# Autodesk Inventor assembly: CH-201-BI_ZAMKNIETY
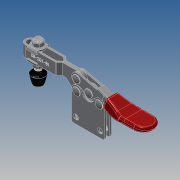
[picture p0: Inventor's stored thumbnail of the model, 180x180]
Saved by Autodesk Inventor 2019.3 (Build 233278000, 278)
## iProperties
Company: ·L?¤¤?
Created: 2010-06
Part Number: CH-201-BI_ZAMKNIETY
Material: Ogólny
Description: STEP AP203
Document SubType Name: Assembly
Designer: CADENGINEERING4
Sending System: SolidWorks 2005179
Preprocessor: SwSTEP 2.0
Title: CH-201-BI.STEP
Author: ·L?¥Î?
Revision Number: ANY
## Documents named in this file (9)
- E:\STRONA\Horizontal toggle clamp\CH-201-BI\CH-201-BI_ZAMKNIETY.iam
- E:\STRONA\Horizontal toggle clamp\CH-201-BI\14134-02___.ipt
- E:\STRONA\Horizontal toggle clamp\CH-201-BI\201-B-04___.ipt
- E:\STRONA\Horizontal toggle clamp\CH-201-BI\201-B-06___.ipt
- E:\STRONA\Horizontal toggle clamp\CH-201-BI\201-BI-02___.ipt
- E:\STRONA\Horizontal toggle clamp\CH-201-BI\FW140___.ipt
- E:\STRONA\Horizontal toggle clamp\CH-201-BI\14134___.ipt
- E:\STRONA\Horizontal toggle clamp\CH-201-BI\201-B___.iam
- E:\STRONA\Horizontal toggle clamp\CH-201-BI\201-BI-01___.ipt
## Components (14 placed, 14 different names)
1. 14134-02_??_1 — Równoległe:3, Zestawiające:1, Zestawiające:5
2. 201-B-04_??_2 — Zestawiające:11, Zestawiające:12, Zestawiające:13
3. 201-B-06_??_3 — Zestawiające:20, Zestawiające:21
4. 201-BI-02_??_4 — Równoległe:1, Zestawiające:7, Zestawiające:8, Zestawiające:9, Zestawiające:10, Zestawiające:22, Zestawiające:25, Zestawiające:26
5. FW140_??_5 — Równoległe:2, Zestawiające:2, Zestawiające:6, Zestawiające:7
6. 14134_??_6 — Równoległe:3, Zestawiające:1, Zestawiające:2, Zestawiające:3, Zestawiające:4, Zestawiające:9
7. 201-B-06_??_7 — Zestawiające:16, Zestawiające:17
8. 201-B-04_??_8 — Zestawiające:11, Zestawiające:12, Zestawiające:13, Zestawiające:14, Zestawiające:15, Zestawiające:18, Zestawiające:19
9. 201-B_??_9 [sub-assembly] — Zestawiające:18, Zestawiające:19, Zestawiające:20, Zestawiające:21, Zestawiające:26, Zestawiające:27, Przejściowe:1
10. 14134-02_??_10 — Zestawiające:3, Zestawiające:6
11. FW140_??_11 — Równoległe:1, Równoległe:2, Zestawiające:4, Zestawiające:5, Zestawiające:8
12. 201-B-06_??_12 — Zestawiające:10, Zestawiające:27
13. 201-B-06_??_13 — Zestawiające:22, Zestawiające:23, Zestawiające:24
14. 201-BI-01_??_14 — Zestawiające:14, Zestawiające:15, Zestawiające:16, Zestawiające:17, Zestawiające:23, Zestawiające:24, Zestawiające:25, Przejściowe:1
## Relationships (31: Mate 27, Flush 3, Transitional 1)
- Równoległe:1 [Flush]: 201-BI-02_??_4 ↔ FW140_??_11
- Równoległe:2 [Flush]: FW140_??_5 ↔ FW140_??_11
- Równoległe:3 [Flush]: 14134-02_??_1 ↔ 14134_??_6
- Zestawiające:1 [Mate]: 14134-02_??_1 ↔ 14134_??_6
- Zestawiające:2 [Mate]: FW140_??_5 ↔ 14134_??_6
- Zestawiające:3 [Mate]: 14134_??_6 ↔ 14134-02_??_10
- Zestawiające:4 [Mate]: 14134_??_6 ↔ FW140_??_11
- Zestawiające:5 [Mate]: 14134-02_??_1 ↔ FW140_??_11
- Zestawiające:6 [Mate]: FW140_??_5 ↔ 14134-02_??_10
- Zestawiające:7 [Mate]: 201-BI-02_??_4 ↔ FW140_??_5
- Zestawiające:8 [Mate]: 201-BI-02_??_4 ↔ FW140_??_11
- Zestawiające:9 [Mate]: 201-BI-02_??_4 ↔ 14134_??_6
- Zestawiające:10 [Mate]: 201-BI-02_??_4 ↔ 201-B-06_??_12
- Zestawiające:11 [Mate]: 201-B-04_??_2 ↔ 201-B-04_??_8
- Zestawiające:12 [Mate]: 201-B-04_??_2 ↔ 201-B-04_??_8
- Zestawiające:13 [Mate]: 201-B-04_??_2 ↔ 201-B-04_??_8
- Zestawiające:14 [Mate]: 201-B-04_??_8 ↔ 201-BI-01_??_14
- Zestawiające:15 [Mate]: 201-B-04_??_8 ↔ 201-BI-01_??_14
- Zestawiające:16 [Mate]: 201-B-06_??_7 ↔ 201-BI-01_??_14
- Zestawiające:17 [Mate]: 201-B-06_??_7 ↔ 201-BI-01_??_14
- Zestawiające:18 [Mate]: 201-B-04_??_8 ↔ 201-B_??_9
- Zestawiające:19 [Mate]: 201-B-04_??_8 ↔ 201-B_??_9
- Zestawiające:20 [Mate]: 201-B-06_??_3 ↔ 201-B_??_9
- Zestawiające:21 [Mate]: 201-B-06_??_3 ↔ 201-B_??_9
- Zestawiające:22 [Mate]: 201-BI-02_??_4 ↔ 201-B-06_??_13
- Zestawiające:23 [Mate]: 201-B-06_??_13 ↔ 201-BI-01_??_14
- Zestawiające:24 [Mate]: 201-B-06_??_13 ↔ 201-BI-01_??_14
- Zestawiające:25 [Mate]: 201-BI-02_??_4 ↔ 201-BI-01_??_14
- Zestawiające:26 [Mate]: 201-BI-02_??_4 ↔ 201-B_??_9
- Zestawiające:27 [Mate]: 201-B_??_9 ↔ 201-B-06_??_12
- Przejściowe:1 [Transitional]: 201-B_??_9 ↔ 201-BI-01_??_14
